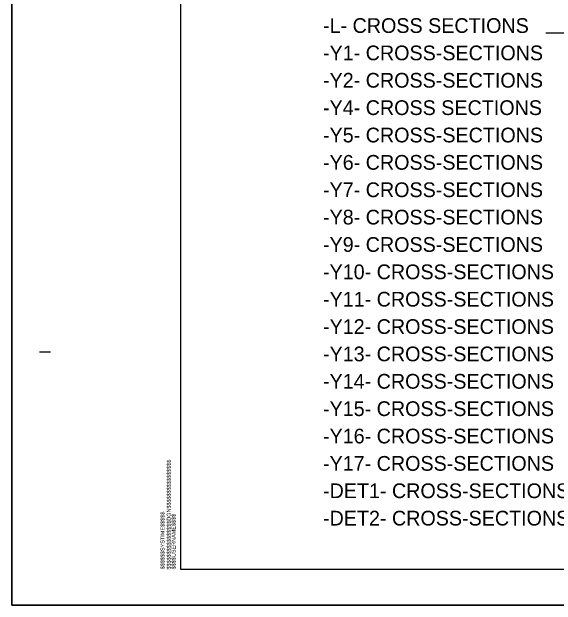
# Model space of a CAD drawing. Extents: x -13516 to -11907, y -4853 to -4486.
# Drawn here: x -12494.8 to -12348.1, y -4802.3 to -4642.4 of the extents above; entities that cross this region are included whole.
import ezdxf

# ---------------------------------------------------------------- set-up
doc = ezdxf.new("R2010")
doc.units = 0
for name, color, linetype in [('Old_Level_2', 7, 'Continuous'), ('Sheet Cutting Line CELL', 7, 'Continuous'), ('Sheet Data Text CELL', 7, 'Continuous'), ('Sheet Detail CELL', 7, 'Continuous'), ('Sheet Plan CELL', 7, 'Continuous'), ('Sheet Plot Border Outside CELL', 7, 'Continuous')]:
    doc.layers.add(name, color=color, linetype=linetype)

msp = doc.modelspace()

# ---------------------------------------------------------------- linework, layer by layer
at = {"layer": 'Old_Level_2'}
msp.add_line((-12350.86, -4648.06), (-12298.77, -4648.06), dxfattribs=at)
at = {"layer": 'Sheet Cutting Line CELL'}
for p, q in [((-12494.81, -4522.91), (-12494.81, -4802.31)), ((-12494.81, -4802.31), (-12063.01, -4802.31))]:
    msp.add_line(p, q, dxfattribs=at)
at = {"layer": 'Sheet Detail CELL'}
for p, q in [((-12449.36, -4532.61), (-12449.36, -4792.61)), ((-12449.36, -4792.61), (-12069.36, -4792.61))]:
    msp.add_line(p, q, dxfattribs=at)
at = {"layer": 'Sheet Plan CELL'}
msp.add_line((-12484.41, -4734.11), (-12487.36, -4734.11), dxfattribs=at)
at = {"layer": 'Sheet Plot Border Outside CELL'}
msp.add_lwpolyline([(-12494.81, -4522.91), (-12063.01, -4522.91), (-12063.01, -4802.31), (-12494.81, -4802.31)], close=True, dxfattribs=at)

# ---------------------------------------------------------------- texts
at = {"layer": 'Old_Level_2'}
for s, p in [('-L- CROSS SECTIONS', (-12410.92, -4648.06)), ('-Y1- CROSS-SECTIONS', (-12410.92, -4655.43)), ('-Y2- CROSS-SECTIONS', (-12410.92, -4662.81)), ('-Y4- CROSS SECTIONS', (-12410.92, -4670.19)), ('-Y5- CROSS-SECTIONS', (-12410.92, -4677.57)), ('-Y6- CROSS-SECTIONS', (-12410.92, -4684.94)), ('-Y7- CROSS-SECTIONS', (-12410.92, -4692.32)), ('-Y8- CROSS-SECTIONS', (-12410.92, -4699.7)), ('-Y9- CROSS-SECTIONS', (-12410.92, -4707.08)), ('-Y10- CROSS-SECTIONS', (-12410.92, -4714.45)), ('-Y11- CROSS-SECTIONS', (-12410.92, -4721.83)), ('-Y12- CROSS-SECTIONS', (-12410.92, -4729.21)), ('-Y13- CROSS-SECTIONS', (-12410.92, -4736.58)), ('-Y14- CROSS-SECTIONS', (-12410.92, -4743.96)), ('-Y15- CROSS-SECTIONS', (-12410.92, -4751.34)), ('-Y16- CROSS-SECTIONS', (-12410.92, -4758.72)), ('-Y17- CROSS-SECTIONS', (-12410.92, -4766.09)), ('-DET1- CROSS-SECTIONS', (-12410.92, -4773.47)), ('-DET2- CROSS-SECTIONS', (-12410.92, -4780.85))]:
    msp.add_text(s, height=3.9724, rotation=0, dxfattribs=at).set_placement(p)
at = {"layer": 'Sheet Data Text CELL'}
for s, p in [('$$$$$$$$$$$$$$$$DGN$$$$$$$$$$$$$$$$', (-12451.98, -4792.71)), ('$$$$$$SYSTIME$$$$$', (-12453.66, -4792.66)), ('$$$$USERNAME$$$$', (-12450.67, -4792.66))]:
    msp.add_text(s, height=1.0711, rotation=90, dxfattribs=at).set_placement(p)

doc.saveas('drawing.dxf')
